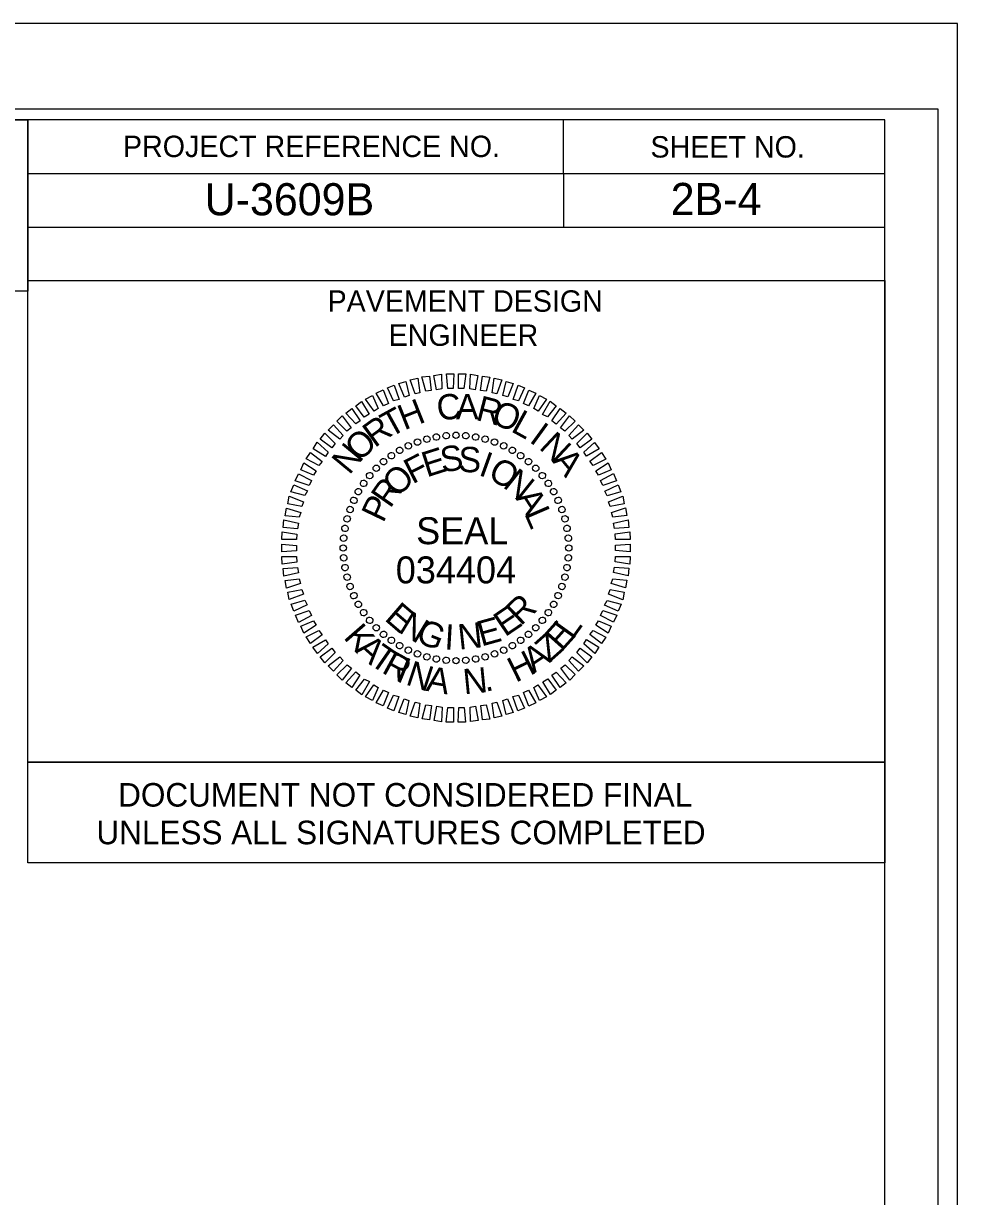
# Model space of a CAD drawing. Extents: x 2455709 to 2456046, y 594728 to 594947.
# Drawn here: x 2456001.9 to 2456045.5, y 594891.8 to 594946.6 of the extents above; entities that cross this region are included whole.
import ezdxf

# ---------------------------------------------------------------- set-up
doc = ezdxf.new("R2010")
doc.units = 0
for name, color, linetype in [('Prop Horizontal Alignment', 7, 'Continuous'), ('Prop Roadway Culvert', 7, 'Continuous'), ('Prop Vertical Profile Curve Label', 7, 'Continuous'), ('Prop Vertical Profile Grade', 7, 'Continuous'), ('Scratch_Level_5', 7, 'Continuous'), ('Scratch_Level_6', 7, 'Continuous')]:
    doc.layers.add(name, color=color, linetype=linetype)

msp = doc.modelspace()

# ---------------------------------------------------------------- linework, layer by layer
at = {"layer": 'Prop Horizontal Alignment'}
for p, q in [((2456002.097, 594934.564), (2456002.097, 594942.079)), ((2456027.099, 594942.064), (2456027.109, 594937.064)), ((2456002.094, 594939.569), (2456042.104, 594939.566)), ((2456002.097, 594937.061), (2456042.104, 594937.066))]:
    msp.add_line(p, q, dxfattribs=at)
for points in [[(2456042.112, 594942.076), (2455742.104, 594942.076), (2455742.104, 594732.076), (2456042.107, 594732.076)], [(2456002.097, 594934.564), (2456042.107, 594934.564), (2456042.107, 594912.064), (2456002.097, 594912.064)]]:
    msp.add_lwpolyline(points, close=True, dxfattribs=at)
at = {"layer": 'Prop Roadway Culvert'}
msp.add_lwpolyline([(2455708.807, 594727.574), (2456045.507, 594727.574), (2456045.507, 594946.574), (2455708.807, 594946.574)], close=True, dxfattribs=at)
at = {"layer": 'Prop Vertical Profile Curve Label'}
msp.add_lwpolyline([(2455979.323, 594942.076), (2456002.097, 594942.079), (2456002.098, 594934.07), (2455979.324, 594934.067)], close=True, dxfattribs=at)
at = {"layer": 'Prop Vertical Profile Grade'}
msp.add_lwpolyline([(2455711.407, 594731.574), (2456044.604, 594731.576), (2456044.607, 594942.574), (2455711.407, 594942.574)], close=True, dxfattribs=at)
at = {"layer": 'Scratch_Level_5'}
for p, q in [((2456021.63, 594927.325), (2456021.63, 594927.325)), ((2456022.091, 594927.343), (2456022.091, 594927.343)), ((2456022.553, 594927.32), (2456022.553, 594927.32)), ((2456019.864, 594926.853), (2456019.864, 594926.853)), ((2456020.281, 594927.028), (2456020.281, 594927.028)), ((2456020.719, 594927.162), (2456020.719, 594927.162)), ((2456021.179, 594927.254), (2456021.179, 594927.254)), ((2456023.006, 594927.254), (2456023.006, 594927.254)), ((2456023.448, 594927.168), (2456023.448, 594927.168)), ((2456023.891, 594927.028), (2456023.891, 594927.028)), ((2456024.314, 594926.847), (2456024.314, 594926.847)), ((2456019.064, 594926.388), (2456019.064, 594926.388)), ((2456019.459, 594926.636), (2456019.459, 594926.636)), ((2456024.727, 594926.644), (2456024.727, 594926.644)), ((2456025.109, 594926.389), (2456025.109, 594926.389)), ((2456018.361, 594925.798), (2456018.361, 594925.798)), ((2456018.702, 594926.119), (2456018.702, 594926.119)), ((2456025.481, 594926.112), (2456025.481, 594926.112)), ((2456025.812, 594925.803), (2456025.812, 594925.803)), ((2456017.775, 594925.096), (2456017.775, 594925.096)), ((2456018.052, 594925.468), (2456018.052, 594925.468)), ((2456026.133, 594925.462), (2456026.133, 594925.462)), ((2456026.401, 594925.099), (2456026.401, 594925.099)), ((2456017.519, 594924.713), (2456017.519, 594924.713)), ((2456026.65, 594924.705), (2456026.65, 594924.705)), ((2456017.316, 594924.3), (2456017.316, 594924.3)), ((2456026.867, 594924.299), (2456026.867, 594924.299)), ((2456017.135, 594923.877), (2456017.135, 594923.877)), ((2456027.042, 594923.883), (2456027.042, 594923.883)), ((2456027.176, 594923.444), (2456027.176, 594923.444)), ((2456016.909, 594922.992), (2456016.909, 594922.992)), ((2456016.996, 594923.434), (2456016.996, 594923.434)), ((2456027.268, 594922.984), (2456027.268, 594922.984)), ((2456016.844, 594922.54), (2456016.844, 594922.54)), ((2456027.338, 594922.534), (2456027.338, 594922.534)), ((2456016.82, 594922.077), (2456016.82, 594922.077)), ((2456027.357, 594922.073), (2456027.357, 594922.073)), ((2456016.839, 594921.616), (2456016.839, 594921.616)), ((2456027.334, 594921.61), (2456027.334, 594921.61)), ((2456016.91, 594921.166), (2456016.91, 594921.166)), ((2456017.002, 594920.706), (2456017.002, 594920.706)), ((2456027.181, 594920.716), (2456027.181, 594920.716)), ((2456027.268, 594921.158), (2456027.268, 594921.158)), ((2456017.135, 594920.267), (2456017.135, 594920.267)), ((2456027.042, 594920.272), (2456027.042, 594920.272)), ((2456017.31, 594919.851), (2456017.31, 594919.851)), ((2456026.861, 594919.849), (2456026.861, 594919.849)), ((2456017.527, 594919.445), (2456017.527, 594919.445)), ((2456026.658, 594919.437), (2456026.658, 594919.437)), ((2456017.776, 594919.05), (2456017.776, 594919.05)), ((2456018.044, 594918.688), (2456018.044, 594918.688)), ((2456026.125, 594918.682), (2456026.125, 594918.682)), ((2456026.402, 594919.054), (2456026.402, 594919.054)), ((2456018.365, 594918.347), (2456018.365, 594918.347)), ((2456018.696, 594918.038), (2456018.696, 594918.038)), ((2456025.475, 594918.031), (2456025.475, 594918.031)), ((2456025.816, 594918.351), (2456025.816, 594918.351)), ((2456019.068, 594917.761), (2456019.068, 594917.761)), ((2456019.45, 594917.506), (2456019.45, 594917.506)), ((2456024.718, 594917.514), (2456024.718, 594917.514)), ((2456025.113, 594917.762), (2456025.113, 594917.762)), ((2456019.863, 594917.303), (2456019.863, 594917.303)), ((2456020.286, 594917.121), (2456020.286, 594917.121)), ((2456020.729, 594916.982), (2456020.729, 594916.982)), ((2456021.172, 594916.895), (2456021.172, 594916.895)), ((2456022.998, 594916.896), (2456022.998, 594916.896)), ((2456023.458, 594916.988), (2456023.458, 594916.988)), ((2456023.896, 594917.121), (2456023.896, 594917.121)), ((2456024.313, 594917.297), (2456024.313, 594917.297)), ((2456021.624, 594916.83), (2456021.624, 594916.83)), ((2456022.086, 594916.807), (2456022.086, 594916.807)), ((2456022.548, 594916.825), (2456022.548, 594916.825))]:
    msp.add_line(p, q, dxfattribs=at)
for points in [[(2456020.68, 594929.397), (2456020.501, 594930.065), (2456020.846, 594930.103), (2456020.932, 594929.433)], [(2456021.183, 594929.468), (2456021.056, 594930.138), (2456021.412, 594930.186), (2456021.434, 594929.504)], [(2456021.706, 594929.53), (2456021.642, 594930.211), (2456021.988, 594930.207), (2456021.958, 594929.524)], [(2456022.21, 594929.528), (2456022.198, 594930.21), (2456022.545, 594930.206), (2456022.462, 594929.522)], [(2456022.735, 594929.506), (2456022.765, 594930.189), (2456023.113, 594930.132), (2456022.988, 594929.468)], [(2456023.24, 594929.431), (2456023.323, 594930.104), (2456023.67, 594930.058), (2456023.493, 594929.404)], [(2456019.166, 594928.95), (2456018.883, 594929.554), (2456019.196, 594929.686), (2456019.428, 594929.018)], [(2456019.678, 594929.127), (2456019.425, 594929.753), (2456019.749, 594929.853), (2456019.897, 594929.205)], [(2456020.179, 594929.272), (2456019.947, 594929.93), (2456020.302, 594930.009), (2456020.398, 594929.329)], [(2456023.777, 594929.325), (2456023.871, 594930.009), (2456024.229, 594929.931), (2456023.999, 594929.276)], [(2456024.283, 594929.197), (2456024.429, 594929.85), (2456024.757, 594929.751), (2456024.505, 594929.128)], [(2456024.759, 594929.017), (2456024.989, 594929.682), (2456025.285, 594929.561), (2456025.001, 594928.947)], [(2456017.805, 594928.192), (2456017.407, 594928.72), (2456017.677, 594928.924), (2456018.033, 594928.322)], [(2456018.262, 594928.462), (2456017.864, 594929.022), (2456018.186, 594929.196), (2456018.459, 594928.592)], [(2456018.709, 594928.722), (2456018.363, 594929.304), (2456018.685, 594929.456), (2456018.938, 594928.82)], [(2456025.234, 594928.825), (2456025.486, 594929.449), (2456025.814, 594929.308), (2456025.467, 594928.714)], [(2456025.721, 594928.593), (2456025.994, 594929.196), (2456026.312, 594929.023), (2456025.923, 594928.47)], [(2456026.135, 594928.317), (2456026.492, 594928.931), (2456026.769, 594928.716), (2456026.368, 594928.195)], [(2456017.412, 594927.87), (2456016.952, 594928.366), (2456017.231, 594928.591), (2456017.609, 594928.01)], [(2456026.571, 594928.009), (2456026.949, 594928.593), (2456027.226, 594928.367), (2456026.773, 594927.866)], [(2456016.658, 594927.164), (2456016.115, 594927.585), (2456016.373, 594927.831), (2456016.823, 594927.335)], [(2456016.998, 594927.538), (2456016.528, 594927.991), (2456016.775, 594928.247), (2456017.194, 594927.688)], [(2456026.975, 594927.691), (2456027.396, 594928.244), (2456027.652, 594927.997), (2456027.178, 594927.537)], [(2456027.359, 594927.33), (2456027.802, 594927.831), (2456028.058, 594927.584), (2456027.52, 594927.165)], [(2456016.298, 594926.759), (2456015.745, 594927.159), (2456015.971, 594927.436), (2456016.441, 594926.951)], [(2456027.733, 594926.959), (2456028.208, 594927.44), (2456028.433, 594927.16), (2456027.884, 594926.752)], [(2456015.99, 594926.355), (2456015.417, 594926.702), (2456015.611, 594927.01), (2456016.123, 594926.557)], [(2456028.055, 594926.555), (2456028.562, 594927.005), (2456028.766, 594926.704), (2456028.185, 594926.358)], [(2456015.682, 594925.93), (2456015.089, 594926.234), (2456015.294, 594926.532), (2456015.847, 594926.122)], [(2456028.336, 594926.13), (2456028.885, 594926.538), (2456029.089, 594926.227), (2456028.486, 594925.923)], [(2456015.438, 594925.474), (2456014.836, 594925.726), (2456014.988, 594926.054), (2456015.561, 594925.676)], [(2456028.616, 594925.673), (2456029.197, 594926.051), (2456029.34, 594925.728), (2456028.746, 594925.476)], [(2456015.237, 594924.988), (2456014.582, 594925.218), (2456014.734, 594925.546), (2456015.338, 594925.221)], [(2456028.834, 594925.226), (2456029.448, 594925.551), (2456029.59, 594925.218), (2456028.943, 594924.997)], [(2456015.035, 594924.523), (2456014.381, 594924.7), (2456014.512, 594925.028), (2456015.147, 594924.745)], [(2456029.032, 594924.736), (2456029.667, 594925.02), (2456029.788, 594924.697), (2456029.14, 594924.517)], [(2456014.887, 594924.017), (2456014.234, 594924.142), (2456014.301, 594924.489), (2456014.967, 594924.238)], [(2456029.208, 594924.235), (2456029.876, 594924.488), (2456029.944, 594924.143), (2456029.286, 594924.016)], [(2456014.759, 594923.511), (2456014.107, 594923.583), (2456014.174, 594923.941), (2456014.839, 594923.732)], [(2456029.343, 594923.734), (2456030, 594923.945), (2456030.07, 594923.589), (2456029.41, 594923.515)], [(2456014.684, 594922.974), (2456014.012, 594923.025), (2456014.048, 594923.383), (2456014.733, 594923.227)], [(2456029.446, 594923.232), (2456030.125, 594923.391), (2456030.163, 594923.035), (2456029.492, 594922.981)], [(2456014.641, 594922.47), (2456013.959, 594922.479), (2456013.974, 594922.825), (2456014.658, 594922.722)], [(2456029.518, 594922.729), (2456030.198, 594922.825), (2456030.226, 594922.469), (2456029.543, 594922.478)], [(2456014.64, 594921.945), (2456013.958, 594921.901), (2456013.952, 594922.258), (2456014.635, 594922.197)], [(2456029.538, 594922.205), (2456030.219, 594922.248), (2456030.225, 594921.892), (2456029.542, 594921.953)], [(2456014.659, 594921.42), (2456013.979, 594921.325), (2456013.951, 594921.681), (2456014.634, 594921.672)], [(2456029.536, 594921.68), (2456030.218, 594921.671), (2456030.204, 594921.325), (2456029.52, 594921.428)], [(2456014.731, 594920.918), (2456014.052, 594920.759), (2456014.014, 594921.115), (2456014.685, 594921.169)], [(2456029.492, 594921.176), (2456030.165, 594921.125), (2456030.129, 594920.767), (2456029.444, 594920.923)], [(2456014.834, 594920.416), (2456014.177, 594920.205), (2456014.108, 594920.561), (2456014.767, 594920.635)], [(2456029.418, 594920.639), (2456030.07, 594920.567), (2456030.003, 594920.209), (2456029.338, 594920.417)], [(2456014.969, 594919.915), (2456014.302, 594919.662), (2456014.233, 594920.007), (2456014.892, 594920.134)], [(2456015.145, 594919.414), (2456014.51, 594919.13), (2456014.389, 594919.453), (2456015.037, 594919.632)], [(2456029.142, 594919.627), (2456029.796, 594919.449), (2456029.665, 594919.122), (2456029.03, 594919.405)], [(2456029.29, 594920.133), (2456029.943, 594920.008), (2456029.876, 594919.661), (2456029.21, 594919.911)], [(2456015.343, 594918.924), (2456014.729, 594918.599), (2456014.587, 594918.932), (2456015.234, 594919.153)], [(2456028.94, 594919.162), (2456029.595, 594918.932), (2456029.443, 594918.604), (2456028.839, 594918.929)], [(2456015.561, 594918.477), (2456014.98, 594918.099), (2456014.838, 594918.422), (2456015.431, 594918.674)], [(2456028.739, 594918.675), (2456029.341, 594918.423), (2456029.19, 594918.096), (2456028.616, 594918.474)], [(2456015.841, 594918.02), (2456015.292, 594917.611), (2456015.088, 594917.923), (2456015.691, 594918.227)], [(2456028.495, 594918.22), (2456029.088, 594917.915), (2456028.883, 594917.618), (2456028.33, 594918.028)], [(2456016.122, 594917.594), (2456015.615, 594917.145), (2456015.411, 594917.446), (2456015.993, 594917.791)], [(2456028.187, 594917.795), (2456028.76, 594917.448), (2456028.566, 594917.14), (2456028.054, 594917.593)], [(2456016.444, 594917.191), (2456015.969, 594916.71), (2456015.744, 594916.99), (2456016.293, 594917.398)], [(2456016.818, 594916.819), (2456016.375, 594916.318), (2456016.119, 594916.566), (2456016.657, 594916.985)], [(2456027.519, 594916.985), (2456028.062, 594916.565), (2456027.804, 594916.319), (2456027.354, 594916.815)], [(2456027.879, 594917.391), (2456028.432, 594916.991), (2456028.206, 594916.714), (2456027.736, 594917.199)], [(2456017.202, 594916.459), (2456016.781, 594915.906), (2456016.525, 594916.153), (2456017, 594916.613)], [(2456027.179, 594916.612), (2456027.649, 594916.159), (2456027.402, 594915.902), (2456026.983, 594916.462)], [(2456017.606, 594916.141), (2456017.228, 594915.557), (2456016.951, 594915.783), (2456017.404, 594916.284)], [(2456018.042, 594915.833), (2456017.685, 594915.218), (2456017.408, 594915.434), (2456017.809, 594915.955)], [(2456026.372, 594915.958), (2456026.77, 594915.43), (2456026.501, 594915.225), (2456026.144, 594915.828)], [(2456026.766, 594916.28), (2456027.225, 594915.784), (2456026.946, 594915.559), (2456026.568, 594916.14)], [(2456018.456, 594915.557), (2456018.183, 594914.954), (2456017.865, 594915.127), (2456018.254, 594915.68)], [(2456018.943, 594915.324), (2456018.691, 594914.701), (2456018.363, 594914.842), (2456018.71, 594915.436)], [(2456025.469, 594915.428), (2456025.814, 594914.846), (2456025.492, 594914.694), (2456025.239, 594915.329)], [(2456025.915, 594915.687), (2456026.313, 594915.128), (2456025.991, 594914.954), (2456025.718, 594915.558)], [(2456019.418, 594915.133), (2456019.188, 594914.468), (2456018.892, 594914.589), (2456019.176, 594915.202)], [(2456019.894, 594914.953), (2456019.748, 594914.299), (2456019.421, 594914.399), (2456019.672, 594915.022)], [(2456020.4, 594914.825), (2456020.307, 594914.141), (2456019.948, 594914.219), (2456020.178, 594914.874)], [(2456020.937, 594914.719), (2456020.854, 594914.046), (2456020.507, 594914.092), (2456020.684, 594914.746)], [(2456021.442, 594914.644), (2456021.412, 594913.961), (2456021.064, 594914.018), (2456021.189, 594914.681)], [(2456022.994, 594914.681), (2456023.121, 594914.012), (2456022.765, 594913.964), (2456022.743, 594914.646)], [(2456023.497, 594914.753), (2456023.676, 594914.085), (2456023.331, 594914.047), (2456023.246, 594914.717)], [(2456023.998, 594914.877), (2456024.23, 594914.22), (2456023.875, 594914.141), (2456023.779, 594914.821)], [(2456024.5, 594915.023), (2456024.752, 594914.397), (2456024.428, 594914.297), (2456024.281, 594914.945)], [(2456025.011, 594915.199), (2456025.294, 594914.596), (2456024.982, 594914.464), (2456024.75, 594915.132)], [(2456021.967, 594914.622), (2456021.979, 594913.94), (2456021.632, 594913.944), (2456021.715, 594914.628)], [(2456022.471, 594914.62), (2456022.535, 594913.939), (2456022.189, 594913.943), (2456022.219, 594914.626)]]:
    msp.add_lwpolyline(points, close=True, dxfattribs=at)
for centre, major_axis in [((2456020.726, 594927.159), (-0.039, 0.146)), ((2456021.175, 594927.258), (-0.026, 0.149)), ((2456021.63, 594927.318), (-0.013, 0.151)), ((2456022.088, 594927.338), (0, 0.151)), ((2456022.547, 594927.318), (0.013, 0.151)), ((2456023.002, 594927.258), (0.026, 0.149)), ((2456023.451, 594927.159), (0.039, 0.146)), ((2456019.457, 594926.633), (-0.076, 0.131)), ((2456019.864, 594926.845), (-0.064, 0.137)), ((2456020.288, 594927.021), (-0.052, 0.142)), ((2456023.889, 594927.021), (0.052, 0.142)), ((2456024.313, 594926.845), (0.064, 0.137)), ((2456024.72, 594926.633), (0.076, 0.131)), ((2456018.705, 594926.107), (-0.097, 0.116)), ((2456019.07, 594926.386), (-0.087, 0.124)), ((2456025.107, 594926.386), (0.087, 0.124)), ((2456025.472, 594926.107), (0.097, 0.116)), ((2456018.367, 594925.797), (-0.107, 0.107)), ((2456025.81, 594925.797), (0.107, 0.107)), ((2456017.777, 594925.094), (-0.124, 0.087)), ((2456018.057, 594925.458), (-0.116, 0.097)), ((2456026.12, 594925.458), (0.116, 0.097)), ((2456026.4, 594925.094), (0.124, 0.087)), ((2456017.53, 594924.707), (-0.131, 0.076)), ((2456026.647, 594924.707), (0.131, 0.076)), ((2456017.143, 594923.875), (-0.142, 0.052)), ((2456017.318, 594924.299), (-0.137, 0.064)), ((2456026.859, 594924.299), (0.137, 0.064)), ((2456027.034, 594923.875), (0.142, 0.052)), ((2456017.005, 594923.437), (-0.146, 0.039)), ((2456027.173, 594923.437), (0.146, 0.039)), ((2456016.905, 594922.989), (-0.149, 0.026)), ((2456027.272, 594922.989), (0.149, 0.026)), ((2456016.845, 594922.534), (-0.151, 0.013)), ((2456027.332, 594922.534), (0.151, 0.013)), ((2456016.825, 594922.075), (-0.151, 0)), ((2456027.352, 594922.075), (0.151, 0)), ((2456016.845, 594921.616), (-0.151, -0.013)), ((2456016.905, 594921.161), (-0.149, -0.026)), ((2456027.272, 594921.161), (0.149, -0.026)), ((2456027.332, 594921.616), (0.151, -0.013)), ((2456017.005, 594920.713), (-0.146, -0.039)), ((2456027.173, 594920.713), (0.146, -0.039)), ((2456017.143, 594920.275), (-0.142, -0.052)), ((2456027.034, 594920.275), (0.142, -0.052)), ((2456017.318, 594919.85), (-0.137, -0.064)), ((2456017.53, 594919.443), (-0.131, -0.076)), ((2456026.647, 594919.443), (0.131, -0.076)), ((2456026.859, 594919.851), (0.137, -0.064)), ((2456017.777, 594919.056), (-0.124, -0.087)), ((2456026.4, 594919.056), (0.124, -0.087)), ((2456018.057, 594918.692), (-0.116, -0.097)), ((2456018.367, 594918.353), (-0.107, -0.107)), ((2456025.81, 594918.353), (0.107, -0.107)), ((2456026.121, 594918.692), (0.116, -0.097)), ((2456018.705, 594918.043), (-0.097, -0.116)), ((2456025.472, 594918.043), (0.097, -0.116)), ((2456019.07, 594917.763), (-0.087, -0.124)), ((2456019.457, 594917.517), (-0.076, -0.131)), ((2456019.864, 594917.305), (-0.064, -0.137)), ((2456024.313, 594917.305), (0.064, -0.137)), ((2456024.72, 594917.517), (0.076, -0.131)), ((2456025.108, 594917.763), (0.087, -0.124)), ((2456020.288, 594917.129), (-0.052, -0.142)), ((2456020.726, 594916.991), (-0.039, -0.146)), ((2456021.175, 594916.892), (-0.026, -0.149)), ((2456021.63, 594916.832), (-0.013, -0.151)), ((2456022.089, 594916.812), (0, -0.151)), ((2456022.547, 594916.832), (0.013, -0.151)), ((2456023.003, 594916.892), (0.026, -0.149)), ((2456023.451, 594916.991), (0.039, -0.146)), ((2456023.889, 594917.129), (0.052, -0.142))]:
    msp.add_ellipse(centre, major_axis=major_axis, ratio=0.999708, dxfattribs=at)
at = {"layer": 'Scratch_Level_6'}
for p, q in [((2456002.099, 594907.366), (2456002.099, 594912.066)), ((2456002.099, 594912.066), (2456042.107, 594912.066)), ((2456042.107, 594912.064), (2456042.107, 594907.364)), ((2456042.107, 594907.366), (2456002.099, 594907.366))]:
    msp.add_line(p, q, dxfattribs=at)

# ---------------------------------------------------------------- texts
at = {"layer": 'Prop Horizontal Alignment'}
for s, height, p in [('PROJECT REFERENCE NO.', 1.00002, (2456006.537, 594940.334)), ('SHEET NO.', 1, (2456031.169, 594940.311)), ('PAVEMENT DESIGN', 1.00002, (2456016.09, 594933.109)), ('ENGINEER', 1, (2456018.944, 594931.516))]:
    msp.add_text(s, height=height, rotation=0, dxfattribs=at).set_placement(p)
at = {"layer": 'Scratch_Level_5'}
for s, height, rotation, p in [('U-3609B', 1.5, 0, (2456010.352, 594937.614)), ('2B-4', 1.5, 0, (2456032.114, 594937.626)), ('H', 1.183, 21.6201, (2456019.673, 594927.563)), ('C', 1.183, 7.2205, (2456021.261, 594928.011)), ('A', 1.183, 0.021, (2456022.088, 594928.088)), ('R', 1.183, 345.6217, (2456022.97, 594928.062)), ('T', 1.183, 28.8204, (2456018.997, 594927.205)), ('O', 1.183, 338.4218, (2456023.676, 594927.917)), ('L', 1.183, 331.2215, (2456024.606, 594927.545)), ('R', 1.183, 36.0212, (2456018.292, 594926.731)), ('I', 1.183, 324.0208, (2456025.465, 594927.056)), ('O', 1.183, 43.2224, (2456017.58, 594926.068)), ('N', 1.183, 316.8196, (2456025.922, 594926.739)), ('N', 1.183, 50.4241, (2456017.108, 594925.451)), ('E', 1.183, 17.6117, (2456020.719, 594925.367)), ('S', 1.183, 8.2563, (2456021.439, 594925.6)), ('S', 1.183, 358.901, (2456022.195, 594925.624)), ('F', 1.183, 26.9677, (2456020.053, 594925.041)), ('I', 1.183, 340.1903, (2456023.099, 594925.493)), ('O', 1.183, 330.8341, (2456023.522, 594925.353)), ('A', 1.183, 309.6178, (2456026.551, 594926.13)), ('O', 1.183, 45.6819, (2456019.372, 594924.41)), ('N', 1.183, 321.4773, (2456024.232, 594924.946)), ('R', 1.183, 55.0403, (2456019.013, 594923.889)), ('A', 1.183, 302.7609, (2456024.839, 594924.411)), ('P', 1.183, 64.3995, (2456018.689, 594923.212)), ('L', 1.183, 293.4015, (2456025.261, 594923.694)), ('SEAL', 1.2588, 0.0006, (2456020.228, 594922.252)), ('034404', 1.2592, 0.0006, (2456019.275, 594920.423)), ('R', 1.183, 43.4821, (2456025.112, 594918.402)), ('E', 1.183, 319.2775, (2456018.705, 594918.731)), ('N', 1.183, 328.6346, (2456019.344, 594918.175)), ('E', 1.183, 34.1247, (2456024.376, 594917.896)), ('K', 1.183, 311.1686, (2456016.8, 594917.886)), ('G', 1.183, 337.9909, (2456020.15, 594917.717)), ('I', 1.183, 356.7018, (2456021.531, 594917.343)), ('N', 1.183, 6.057, (2456022.235, 594917.323)), ('E', 1.183, 15.4124, (2456023.271, 594917.467)), ('E', 1.183, 48.1249, (2456027.026, 594917.207)), ('L', 1.183, 54.2997, (2456027.521, 594917.753)), ('Z', 1.183, 41.5854, (2456026.44, 594916.691)), ('A', 1.183, 318.0728, (2456017.342, 594917.266)), ('T', 1.183, 325.3226, (2456017.988, 594916.69)), ('A', 1.183, 34.3357, (2456025.727, 594916.2)), ('R', 1.183, 331.3054, (2456018.572, 594916.279)), ('I', 1.183, 337.7105, (2456019.241, 594915.909)), ('H', 1.183, 26.3758, (2456024.88, 594915.77)), ('N', 1.183, 341.8314, (2456019.692, 594915.711)), ('A', 1.183, 350.252, (2456020.651, 594915.41)), ('N', 1.183, 5.596, (2456022.47, 594915.234)), ('.', 1.183, 14.0166, (2456023.469, 594915.346))]:
    msp.add_text(s, height=height, rotation=rotation, dxfattribs=at).set_placement(p)
at = {"layer": 'Scratch_Level_6'}
for s, p in [('DOCUMENT NOT CONSIDERED FINAL', (2456006.313, 594909.997)), ('UNLESS ALL SIGNATURES COMPLETED', (2456005.299, 594908.237))]:
    msp.add_text(s, height=1.1, dxfattribs=at).set_placement(p)

doc.saveas('drawing.dxf')
